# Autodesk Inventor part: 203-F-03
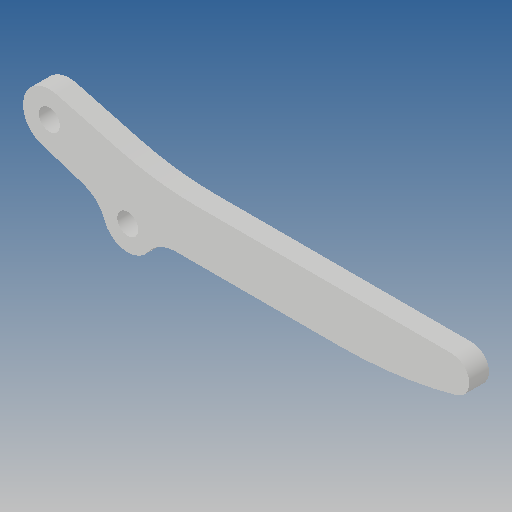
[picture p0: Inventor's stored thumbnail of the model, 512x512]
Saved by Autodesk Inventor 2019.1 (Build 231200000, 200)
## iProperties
Created: 2011-05
Part Number: 203-F-03
Material: Ogólny
Document SubType Name: Modeling
Designer: CADENGINEERING4
Density: 1 g/cm^3
Appearance: Domyślna
Author: CADENGINEERING4
Revision Number: ÈÎºÎ
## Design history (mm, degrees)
feature "Í¹Ì¨-À­Éì1"
node "Bryła1"
